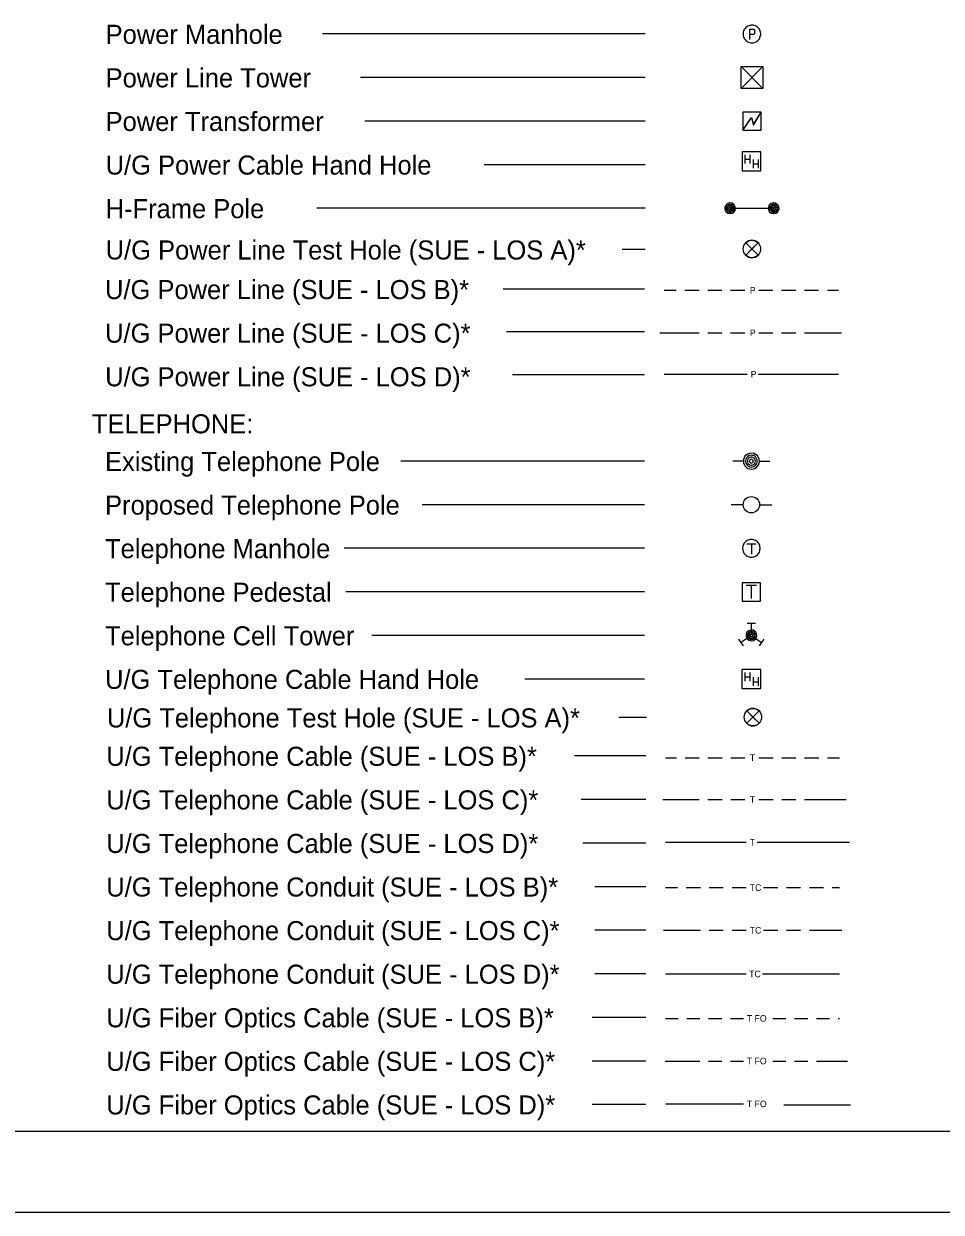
# Model space of a CAD drawing. Extents: x 1552903 to 1553044, y 811448 to 811540.
# Drawn here: x 1552973.4 to 1553008.81, y 811448.42 to 811494.28 of the extents above; entities that cross this region are included whole.
import ezdxf

# ---------------------------------------------------------------- set-up
doc = ezdxf.new("R2010")
doc.units = 0
for name, color, linetype in [('Exist DTM Breakline', 7, 'Continuous'), ('Exist Structure Major Bridge WW', 7, 'Continuous'), ('Exist Utilities Power Test Hole SUE LOS A CELL', 7, 'Continuous'), ('Exist Utilities Telephone Test Hole SUE LOS A CELL', 7, 'Continuous'), ('z - Construction', 7, 'Continuous')]:
    doc.layers.add(name, color=color, linetype=linetype)

msp = doc.modelspace()

# ---------------------------------------------------------------- linework, layer by layer
at = {"layer": 'Exist DTM Breakline'}
for p, q in [((1553001.602, 811494.039), (1553001.602, 811493.895)), ((1552997.385, 811493.884), (1552984.928, 811493.884)), ((1553001.574, 811493.867), (1553001.421, 811493.867)), ((1553001.928, 811492.624), (1553001.088, 811491.784)), ((1553001.928, 811491.784), (1553001.088, 811492.624)), ((1552997.385, 811492.202), (1552986.399, 811492.202)), ((1552997.385, 811490.521), (1552986.569, 811490.521)), ((1553001.231, 811489.225), (1553001.231, 811488.886)), ((1553001.231, 811489.053), (1553001.424, 811489.053)), ((1553001.424, 811489.225), (1553001.424, 811488.886)), ((1553001.554, 811489.041), (1553001.554, 811488.702)), ((1553001.554, 811488.868), (1553001.748, 811488.868)), ((1553001.748, 811489.041), (1553001.748, 811488.702)), ((1552997.385, 811488.839), (1552991.172, 811488.839)), ((1552997.385, 811487.158), (1552984.715, 811487.158)), ((1553000.665, 811487.158), (1553002.347, 811487.158)), ((1552997.385, 811485.562), (1552996.491, 811485.562)), ((1552997.362, 811484.035), (1552991.904, 811484.035)), ((1552998.12, 811483.993), (1552998.582, 811483.993)), ((1552998.919, 811483.993), (1552999.465, 811483.993)), ((1552999.801, 811483.993), (1553000.348, 811483.993)), ((1553000.684, 811483.993), (1553001.231, 811483.993)), ((1553001.769, 811483.993), (1553002.315, 811483.993)), ((1553002.652, 811483.993), (1553003.198, 811483.993)), ((1553003.534, 811483.993), (1553004.081, 811483.993)), ((1553004.417, 811483.993), (1553004.846, 811483.993)), ((1552997.362, 811482.385), (1552992.033, 811482.385)), ((1552997.95, 811482.353), (1552999.465, 811482.353)), ((1552999.801, 811482.353), (1553000.348, 811482.353)), ((1553000.684, 811482.353), (1553001.231, 811482.353)), ((1553001.769, 811482.353), (1553002.315, 811482.353)), ((1553002.652, 811482.353), (1553003.198, 811482.353)), ((1553003.534, 811482.353), (1553004.966, 811482.353)), ((1552997.362, 811480.736), (1552992.259, 811480.736)), ((1552998.12, 811480.759), (1553001.322, 811480.759)), ((1553001.743, 811480.759), (1553004.846, 811480.759)), ((1552997.362, 811477.402), (1552987.955, 811477.402)), ((1553001.173, 811477.402), (1553000.769, 811477.402)), ((1553001.793, 811477.402), (1553002.197, 811477.402)), ((1552997.362, 811475.72), (1552988.781, 811475.72)), ((1553001.171, 811475.719), (1553000.698, 811475.719)), ((1553001.801, 811475.719), (1553002.274, 811475.719)), ((1553001.658, 811474.197), (1553001.311, 811474.197)), ((1553001.483, 811474.197), (1553001.483, 811473.815)), ((1552997.362, 811474.039), (1552985.771, 811474.039)), ((1552997.362, 811472.357), (1552985.83, 811472.357)), ((1553001.286, 811472.611), (1553001.68, 811472.611)), ((1553001.483, 811472.104), (1553001.483, 811472.611)), ((1553001.325, 811471.152), (1553001.641, 811471.152)), ((1553001.483, 811470.883), (1553001.483, 811471.152)), ((1552997.362, 811470.676), (1552986.833, 811470.676)), ((1553001.184, 811470.274), (1553001.003, 811470.532)), ((1553001.314, 811470.557), (1553001.094, 811470.403)), ((1553001.653, 811470.558), (1553001.873, 811470.403)), ((1553001.963, 811470.533), (1553001.782, 811470.274)), ((1553001.225, 811469.249), (1553001.225, 811468.91)), ((1553001.419, 811469.249), (1553001.419, 811468.91)), ((1552997.362, 811468.994), (1552992.735, 811468.994)), ((1553001.225, 811469.076), (1553001.419, 811469.076)), ((1553001.549, 811469.064), (1553001.549, 811468.725)), ((1553001.549, 811468.891), (1553001.742, 811468.891)), ((1553001.742, 811469.064), (1553001.742, 811468.725)), ((1552997.431, 811467.508), (1552996.367, 811467.508)), ((1552997.408, 811466.026), (1552994.652, 811466.026)), ((1552998.166, 811465.959), (1552998.588, 811465.959)), ((1552998.925, 811465.959), (1552999.471, 811465.959)), ((1552999.807, 811465.959), (1553000.354, 811465.959)), ((1553000.69, 811465.959), (1553001.237, 811465.959)), ((1553001.775, 811465.959), (1553002.321, 811465.959)), ((1553002.658, 811465.959), (1553003.204, 811465.959)), ((1553003.54, 811465.959), (1553004.087, 811465.959)), ((1553004.423, 811465.959), (1553004.892, 811465.959)), ((1552997.408, 811464.345), (1552994.917, 811464.345)), ((1552998.061, 811464.345), (1552999.471, 811464.345)), ((1552999.807, 811464.345), (1553000.354, 811464.345)), ((1553000.69, 811464.345), (1553001.237, 811464.345)), ((1553001.775, 811464.345), (1553002.321, 811464.345)), ((1553002.658, 811464.345), (1553003.204, 811464.345)), ((1553003.54, 811464.345), (1553005.141, 811464.345)), ((1552997.408, 811462.663), (1552994.982, 811462.663)), ((1552998.166, 811462.693), (1553001.287, 811462.693)), ((1553001.708, 811462.693), (1553005.271, 811462.693)), ((1552997.408, 811460.982), (1552995.435, 811460.982)), ((1552998.166, 811460.946), (1552998.636, 811460.946)), ((1552998.972, 811460.946), (1552999.518, 811460.946)), ((1552999.855, 811460.946), (1553000.401, 811460.946)), ((1553000.737, 811460.946), (1553001.284, 811460.946)), ((1553001.957, 811460.946), (1553002.503, 811460.946)), ((1553002.839, 811460.946), (1553003.386, 811460.946)), ((1553003.722, 811460.946), (1553004.269, 811460.946)), ((1553004.605, 811460.946), (1553004.892, 811460.946)), ((1552997.408, 811459.3), (1552995.435, 811459.3)), ((1552998.086, 811459.3), (1552999.518, 811459.3)), ((1552999.855, 811459.3), (1553000.401, 811459.3)), ((1553000.737, 811459.3), (1553001.284, 811459.3)), ((1553001.957, 811459.3), (1553002.503, 811459.3)), ((1553002.839, 811459.3), (1553003.386, 811459.3)), ((1553003.722, 811459.3), (1553004.973, 811459.3)), ((1552997.408, 811457.619), (1552995.435, 811457.619)), ((1552998.166, 811457.614), (1553001.284, 811457.614)), ((1553001.915, 811457.614), (1553004.892, 811457.614)), ((1552997.408, 811455.937), (1552995.338, 811455.937)), ((1552998.166, 811455.9), (1552998.657, 811455.9)), ((1552998.993, 811455.9), (1552999.497, 811455.9)), ((1552999.834, 811455.9), (1553000.338, 811455.9)), ((1553000.674, 811455.9), (1553001.179, 811455.9)), ((1553002.314, 811455.9), (1553002.818, 811455.9)), ((1553003.155, 811455.9), (1553003.659, 811455.9)), ((1553003.996, 811455.9), (1553004.5, 811455.9)), ((1553004.836, 811455.9), (1553004.892, 811455.9)), ((1552997.408, 811454.255), (1552995.338, 811454.255)), ((1552998.15, 811454.255), (1552999.497, 811454.255)), ((1552999.834, 811454.255), (1553000.338, 811454.255)), ((1553000.674, 811454.255), (1553001.179, 811454.255)), ((1553002.314, 811454.255), (1553002.818, 811454.255)), ((1553003.155, 811454.255), (1553003.659, 811454.255)), ((1553003.996, 811454.255), (1553005.199, 811454.255)), ((1552997.408, 811452.574), (1552995.338, 811452.574)), ((1552998.166, 811452.601), (1553001.182, 811452.601)), ((1553002.737, 811452.569), (1553005.312, 811452.569))]:
    msp.add_line(p, q, dxfattribs=at)
for points in [[(1553001.506, 811494.225), (1553001.462, 811494.222), (1553001.421, 811494.214), (1553001.38, 811494.201), (1553001.342, 811494.181), (1553001.307, 811494.16), (1553001.274, 811494.132), (1553001.244, 811494.1), (1553001.219, 811494.067), (1553001.197, 811494.029), (1553001.184, 811493.988), (1553001.173, 811493.947), (1553001.167, 811493.906), (1553001.167, 811493.862), (1553001.173, 811493.821), (1553001.184, 811493.777), (1553001.197, 811493.739), (1553001.219, 811493.701), (1553001.244, 811493.668), (1553001.274, 811493.635), (1553001.307, 811493.608), (1553001.342, 811493.586), (1553001.38, 811493.567), (1553001.421, 811493.553), (1553001.465, 811493.545), (1553001.506, 811493.542), (1553001.55, 811493.545), (1553001.591, 811493.553), (1553001.632, 811493.567), (1553001.67, 811493.586), (1553001.705, 811493.608), (1553001.738, 811493.635), (1553001.768, 811493.668), (1553001.793, 811493.701), (1553001.815, 811493.739), (1553001.828, 811493.78), (1553001.839, 811493.821), (1553001.845, 811493.862), (1553001.845, 811493.906), (1553001.839, 811493.947), (1553001.828, 811493.99), (1553001.815, 811494.029), (1553001.793, 811494.067), (1553001.768, 811494.1), (1553001.738, 811494.132), (1553001.705, 811494.16), (1553001.67, 811494.181), (1553001.632, 811494.201), (1553001.591, 811494.214), (1553001.547, 811494.222), (1553001.506, 811494.225)], [(1553001.421, 811493.665), (1553001.421, 811493.867), (1553001.421, 811494.067), (1553001.574, 811494.067)], [(1553001.574, 811494.067), (1553001.585, 811494.064), (1553001.593, 811494.059), (1553001.599, 811494.05), (1553001.602, 811494.039)], [(1553001.602, 811493.895), (1553001.599, 811493.884), (1553001.593, 811493.876), (1553001.585, 811493.87), (1553001.574, 811493.867)], [(1553001.928, 811491.784), (1553001.088, 811491.784), (1553001.088, 811492.624), (1553001.928, 811492.624), (1553001.928, 811491.784), (1553001.088, 811491.784), (1553001.088, 811492.624), (1553001.928, 811492.624), (1553001.928, 811491.784)], [(1553001.156, 811490.17), (1553001.486, 811490.646), (1553001.567, 811490.387), (1553001.856, 811490.871)], [(1553001.156, 811490.17), (1553001.489, 811490.665), (1553001.564, 811490.368), (1553001.856, 811490.871)], [(1553001.156, 811490.17), (1553001.856, 811490.17), (1553001.856, 811490.871), (1553001.156, 811490.871), (1553001.156, 811490.17)], [(1553001.127, 811488.609), (1553001.85, 811488.609), (1553001.85, 811489.333), (1553001.127, 811489.333), (1553001.127, 811488.609)], [(1553000.818, 811487.158), (1553000.814, 811487.195), (1553000.802, 811487.228), (1553000.781, 811487.257), (1553000.756, 811487.282), (1553000.727, 811487.298), (1553000.69, 811487.307), (1553000.657, 811487.311), (1553000.62, 811487.302), (1553000.586, 811487.29), (1553000.562, 811487.269), (1553000.537, 811487.24), (1553000.52, 811487.211), (1553000.512, 811487.174), (1553000.512, 811487.141), (1553000.52, 811487.104), (1553000.537, 811487.075), (1553000.562, 811487.046), (1553000.586, 811487.025), (1553000.62, 811487.013), (1553000.657, 811487.004), (1553000.69, 811487.009), (1553000.727, 811487.017), (1553000.756, 811487.033), (1553000.781, 811487.058), (1553000.802, 811487.087), (1553000.814, 811487.12), (1553000.818, 811487.158)], [(1553000.769, 811487.158), (1553000.764, 811487.187), (1553000.752, 811487.215), (1553000.731, 811487.236), (1553000.707, 811487.253), (1553000.682, 811487.261), (1553000.649, 811487.261), (1553000.624, 811487.253), (1553000.599, 811487.236), (1553000.578, 811487.215), (1553000.566, 811487.187), (1553000.562, 811487.158), (1553000.566, 811487.129), (1553000.578, 811487.1), (1553000.599, 811487.079), (1553000.624, 811487.062), (1553000.649, 811487.054), (1553000.682, 811487.054), (1553000.707, 811487.062), (1553000.731, 811487.079), (1553000.752, 811487.1), (1553000.764, 811487.129), (1553000.769, 811487.158)], [(1553000.715, 811487.158), (1553000.711, 811487.178), (1553000.698, 811487.195), (1553000.682, 811487.203), (1553000.661, 811487.207), (1553000.64, 811487.199), (1553000.624, 811487.187), (1553000.615, 811487.166), (1553000.615, 811487.149), (1553000.624, 811487.129), (1553000.64, 811487.116), (1553000.661, 811487.108), (1553000.682, 811487.112), (1553000.698, 811487.12), (1553000.711, 811487.137), (1553000.715, 811487.158)], [(1553002.5, 811487.158), (1553002.496, 811487.195), (1553002.483, 811487.228), (1553002.463, 811487.257), (1553002.438, 811487.282), (1553002.409, 811487.298), (1553002.371, 811487.307), (1553002.338, 811487.311), (1553002.301, 811487.302), (1553002.268, 811487.29), (1553002.243, 811487.269), (1553002.219, 811487.24), (1553002.202, 811487.211), (1553002.194, 811487.174), (1553002.194, 811487.141), (1553002.202, 811487.104), (1553002.219, 811487.075), (1553002.243, 811487.046), (1553002.268, 811487.025), (1553002.301, 811487.013), (1553002.338, 811487.004), (1553002.371, 811487.009), (1553002.409, 811487.017), (1553002.438, 811487.033), (1553002.463, 811487.058), (1553002.483, 811487.087), (1553002.496, 811487.12), (1553002.5, 811487.158)], [(1553002.45, 811487.158), (1553002.446, 811487.187), (1553002.434, 811487.215), (1553002.413, 811487.236), (1553002.388, 811487.253), (1553002.363, 811487.261), (1553002.33, 811487.261), (1553002.305, 811487.253), (1553002.28, 811487.236), (1553002.26, 811487.215), (1553002.247, 811487.187), (1553002.243, 811487.158), (1553002.247, 811487.129), (1553002.26, 811487.1), (1553002.28, 811487.079), (1553002.305, 811487.062), (1553002.33, 811487.054), (1553002.363, 811487.054), (1553002.388, 811487.062), (1553002.413, 811487.079), (1553002.434, 811487.1), (1553002.446, 811487.129), (1553002.45, 811487.158)], [(1553002.396, 811487.158), (1553002.392, 811487.178), (1553002.38, 811487.195), (1553002.363, 811487.203), (1553002.343, 811487.207), (1553002.322, 811487.199), (1553002.305, 811487.187), (1553002.297, 811487.166), (1553002.297, 811487.149), (1553002.305, 811487.129), (1553002.322, 811487.116), (1553002.343, 811487.108), (1553002.363, 811487.112), (1553002.38, 811487.12), (1553002.392, 811487.137), (1553002.396, 811487.158)], [(1553001.713, 811477.402), (1553001.706, 811477.458), (1553001.688, 811477.507), (1553001.657, 811477.551), (1553001.619, 811477.588), (1553001.576, 811477.613), (1553001.52, 811477.625), (1553001.47, 811477.632), (1553001.415, 811477.619), (1553001.365, 811477.601), (1553001.328, 811477.57), (1553001.291, 811477.526), (1553001.266, 811477.483), (1553001.253, 811477.427), (1553001.253, 811477.377), (1553001.266, 811477.321), (1553001.291, 811477.278), (1553001.328, 811477.234), (1553001.365, 811477.203), (1553001.415, 811477.185), (1553001.47, 811477.172), (1553001.52, 811477.179), (1553001.576, 811477.191), (1553001.619, 811477.216), (1553001.657, 811477.253), (1553001.688, 811477.297), (1553001.706, 811477.346), (1553001.713, 811477.402)], [(1553001.638, 811477.402), (1553001.632, 811477.445), (1553001.613, 811477.489), (1553001.582, 811477.52), (1553001.545, 811477.545), (1553001.508, 811477.557), (1553001.458, 811477.557), (1553001.421, 811477.545), (1553001.384, 811477.52), (1553001.353, 811477.489), (1553001.334, 811477.445), (1553001.328, 811477.402), (1553001.334, 811477.359), (1553001.353, 811477.315), (1553001.384, 811477.284), (1553001.421, 811477.259), (1553001.458, 811477.247), (1553001.508, 811477.247), (1553001.545, 811477.259), (1553001.582, 811477.284), (1553001.613, 811477.315), (1553001.632, 811477.359), (1553001.638, 811477.402)], [(1553001.557, 811477.402), (1553001.551, 811477.433), (1553001.533, 811477.458), (1553001.508, 811477.47), (1553001.477, 811477.476), (1553001.446, 811477.464), (1553001.421, 811477.445), (1553001.408, 811477.415), (1553001.408, 811477.389), (1553001.421, 811477.359), (1553001.446, 811477.34), (1553001.477, 811477.328), (1553001.508, 811477.334), (1553001.533, 811477.346), (1553001.551, 811477.371), (1553001.557, 811477.402)], [(1553001.483, 811474.38), (1553001.439, 811474.377), (1553001.398, 811474.369), (1553001.357, 811474.356), (1553001.319, 811474.336), (1553001.284, 811474.315), (1553001.251, 811474.287), (1553001.221, 811474.255), (1553001.196, 811474.222), (1553001.174, 811474.184), (1553001.161, 811474.143), (1553001.15, 811474.102), (1553001.144, 811474.061), (1553001.144, 811474.017), (1553001.15, 811473.976), (1553001.161, 811473.932), (1553001.174, 811473.894), (1553001.196, 811473.856), (1553001.221, 811473.823), (1553001.251, 811473.79), (1553001.284, 811473.763), (1553001.319, 811473.741), (1553001.357, 811473.722), (1553001.398, 811473.708), (1553001.442, 811473.7), (1553001.483, 811473.698), (1553001.527, 811473.7), (1553001.568, 811473.708), (1553001.609, 811473.722), (1553001.647, 811473.741), (1553001.682, 811473.763), (1553001.715, 811473.79), (1553001.745, 811473.823), (1553001.77, 811473.856), (1553001.792, 811473.894), (1553001.805, 811473.935), (1553001.816, 811473.976), (1553001.822, 811474.017), (1553001.822, 811474.061), (1553001.816, 811474.102), (1553001.805, 811474.145), (1553001.792, 811474.184), (1553001.77, 811474.222), (1553001.745, 811474.255), (1553001.715, 811474.287), (1553001.682, 811474.315), (1553001.647, 811474.336), (1553001.609, 811474.356), (1553001.568, 811474.369), (1553001.524, 811474.377), (1553001.483, 811474.38)], [(1553001.129, 811472.003), (1553001.837, 811472.003), (1553001.837, 811472.711), (1553001.129, 811472.711), (1553001.129, 811472.003)], [(1553001.636, 811470.676), (1553001.632, 811470.713), (1553001.619, 811470.746), (1553001.599, 811470.775), (1553001.574, 811470.8), (1553001.545, 811470.816), (1553001.508, 811470.825), (1553001.475, 811470.829), (1553001.437, 811470.821), (1553001.404, 811470.808), (1553001.38, 811470.787), (1553001.355, 811470.758), (1553001.338, 811470.73), (1553001.33, 811470.692), (1553001.33, 811470.659), (1553001.338, 811470.622), (1553001.355, 811470.593), (1553001.38, 811470.564), (1553001.404, 811470.543), (1553001.437, 811470.531), (1553001.475, 811470.523), (1553001.508, 811470.527), (1553001.545, 811470.535), (1553001.574, 811470.552), (1553001.599, 811470.576), (1553001.619, 811470.605), (1553001.632, 811470.639), (1553001.636, 811470.676)], [(1553001.586, 811470.676), (1553001.582, 811470.705), (1553001.57, 811470.734), (1553001.549, 811470.754), (1553001.524, 811470.771), (1553001.5, 811470.779), (1553001.466, 811470.779), (1553001.442, 811470.771), (1553001.417, 811470.754), (1553001.396, 811470.734), (1553001.384, 811470.705), (1553001.38, 811470.676), (1553001.384, 811470.647), (1553001.396, 811470.618), (1553001.417, 811470.597), (1553001.442, 811470.581), (1553001.466, 811470.572), (1553001.5, 811470.572), (1553001.524, 811470.581), (1553001.549, 811470.597), (1553001.57, 811470.618), (1553001.582, 811470.647), (1553001.586, 811470.676)], [(1553001.533, 811470.676), (1553001.528, 811470.696), (1553001.516, 811470.713), (1553001.5, 811470.721), (1553001.479, 811470.725), (1553001.458, 811470.717), (1553001.442, 811470.705), (1553001.433, 811470.684), (1553001.433, 811470.667), (1553001.442, 811470.647), (1553001.458, 811470.634), (1553001.479, 811470.626), (1553001.5, 811470.63), (1553001.516, 811470.639), (1553001.528, 811470.655), (1553001.533, 811470.676)], [(1553001.121, 811468.632), (1553001.845, 811468.632), (1553001.845, 811469.356), (1553001.121, 811469.356), (1553001.121, 811468.632)]]:
    msp.add_lwpolyline(points, dxfattribs=at)
for points in [[(1553000.665, 811486.951), (1553000.752, 811486.967), (1553000.81, 811487.009), (1553000.856, 811487.067), (1553000.872, 811487.145), (1553000.864, 811487.22), (1553000.822, 811487.294), (1553000.74, 811487.356), (1553000.644, 811487.364), (1553000.562, 811487.34), (1553000.496, 811487.282), (1553000.462, 811487.203), (1553000.462, 811487.112), (1553000.496, 811487.033), (1553000.57, 811486.971)], [(1553002.347, 811486.951), (1553002.434, 811486.967), (1553002.492, 811487.009), (1553002.537, 811487.067), (1553002.554, 811487.145), (1553002.545, 811487.22), (1553002.504, 811487.294), (1553002.421, 811487.356), (1553002.326, 811487.364), (1553002.243, 811487.34), (1553002.177, 811487.282), (1553002.144, 811487.203), (1553002.144, 811487.112), (1553002.177, 811487.033), (1553002.252, 811486.971)], [(1553001.483, 811477.092), (1553001.613, 811477.116), (1553001.7, 811477.179), (1553001.769, 811477.266), (1553001.793, 811477.383), (1553001.781, 811477.495), (1553001.719, 811477.607), (1553001.595, 811477.7), (1553001.452, 811477.712), (1553001.328, 811477.675), (1553001.229, 811477.588), (1553001.179, 811477.47), (1553001.179, 811477.334), (1553001.229, 811477.216), (1553001.34, 811477.123)], [(1553001.483, 811470.469), (1553001.57, 811470.485), (1553001.628, 811470.527), (1553001.673, 811470.585), (1553001.69, 811470.663), (1553001.682, 811470.738), (1553001.64, 811470.812), (1553001.557, 811470.874), (1553001.462, 811470.883), (1553001.38, 811470.858), (1553001.313, 811470.8), (1553001.28, 811470.721), (1553001.28, 811470.63), (1553001.313, 811470.552), (1553001.388, 811470.489)]]:
    msp.add_lwpolyline(points, close=True, dxfattribs=at)
msp.add_circle((1553001.483, 811475.72), 0.315, dxfattribs=at)
at = {"layer": 'Exist Structure Major Bridge WW'}
msp.add_line((1552905.688, 811451.545), (1553041.103, 811451.545), dxfattribs=at)
at = {"layer": 'Exist Utilities Power Test Hole SUE LOS A CELL'}
for points in [[(1553001.742, 811485.826), (1553001.266, 811485.351), (1553001.504, 811485.588), (1553001.266, 811485.826), (1553001.742, 811485.351)], [(1553001.266, 811485.826), (1553001.504, 811485.588), (1553001.742, 811485.826)], [(1553001.742, 811485.351), (1553001.504, 811485.588), (1553001.266, 811485.351)]]:
    msp.add_lwpolyline(points, dxfattribs=at)
msp.add_circle((1553001.504, 811485.588), 0.336, dxfattribs=at)
for start, end in [(45, 135), (225, 315)]:
    msp.add_arc((1553001.504, 811485.588), 0.336, start, end, dxfattribs=at)
at = {"layer": 'Exist Utilities Telephone Test Hole SUE LOS A CELL'}
for points in [[(1553001.781, 811467.761), (1553001.306, 811467.286), (1553001.544, 811467.524), (1553001.306, 811467.761), (1553001.781, 811467.286)], [(1553001.306, 811467.761), (1553001.544, 811467.524), (1553001.781, 811467.761)], [(1553001.781, 811467.286), (1553001.544, 811467.524), (1553001.306, 811467.286)]]:
    msp.add_lwpolyline(points, dxfattribs=at)
msp.add_circle((1553001.544, 811467.524), 0.336, dxfattribs=at)
for start, end in [(45, 135), (225, 315)]:
    msp.add_arc((1553001.544, 811467.524), 0.336, start, end, dxfattribs=at)
at = {"layer": 'z - Construction'}
msp.add_line((1552902.563, 811448.42), (1553044.23, 811448.42), dxfattribs=at)

# ---------------------------------------------------------------- texts
at = {"layer": 'Exist DTM Breakline'}
for s, height, p in [('Power Manhole', 0.73569, (1552976.557, 811493.502)), ('Power Line Tower', 0.73569, (1552976.557, 811491.822)), ('Power Transformer', 0.73569, (1552976.556, 811490.14)), ('U/G Power Cable Hand Hole', 0.73569, (1552976.558, 811488.458)), ('H-Frame Pole', 0.73569, (1552976.558, 811486.776)), ('U/G Power Line Test Hole (SUE - LOS A)*', 0.73569, (1552976.558, 811485.181)), ('U/G Power Line (SUE - LOS B)*', 0.73569, (1552976.535, 811483.653)), ('P', 0.252, (1553001.424, 811483.867)), ('U/G Power Line (SUE - LOS C)*', 0.73569, (1552976.537, 811481.971)), ('P', 0.252, (1553001.424, 811482.227)), ('U/G Power Line (SUE - LOS D)*', 0.73569, (1552976.539, 811480.288)), ('P', 0.252, (1553001.457, 811480.633)), ('TELEPHONE:', 0.7357, (1552976.025, 811478.474)), ('Existing Telephone Pole', 0.73569, (1552976.535, 811477.02)), ('Proposed Telephone Pole', 0.73569, (1552976.535, 811475.339)), ('Telephone Manhole', 0.73569, (1552976.535, 811473.657)), ('Telephone Pedestal', 0.73569, (1552976.535, 811471.976)), ('Telephone Cell Tower', 0.73569, (1552976.536, 811470.294)), ('U/G Telephone Cable Hand Hole', 0.73569, (1552976.536, 811468.613)), ('U/G Telephone Test Hole (SUE - LOS A)*', 0.73569, (1552976.605, 811467.126)), ('U/G Telephone Cable (SUE - LOS B)*', 0.73569, (1552976.582, 811465.645)), ('T', 0.252, (1553001.426, 811465.833)), ('U/G Telephone Cable (SUE - LOS C)*', 0.73569, (1552976.582, 811463.963)), ('T', 0.252, (1553001.426, 811464.219)), ('U/G Telephone Cable (SUE - LOS D)*', 0.73569, (1552976.582, 811462.282)), ('T', 0.252, (1553001.417, 811462.567)), ('U/G Telephone Conduit (SUE - LOS B)*', 0.73569, (1552976.582, 811460.6)), ('TC', 0.2522, (1553001.419, 811460.82)), ('U/G Telephone Conduit (SUE - LOS C)*', 0.73569, (1552976.582, 811458.919)), ('TC', 0.2522, (1553001.419, 811459.174)), ('U/G Telephone Conduit (SUE - LOS D)*', 0.73569, (1552976.582, 811457.237)), ('TC', 0.2522, (1553001.398, 811457.488)), ('U/G Fiber Optics Cable (SUE - LOS B)*', 0.73569, (1552976.582, 811455.555)), ('T FO', 0.2522, (1553001.305, 811455.774)), ('U/G Fiber Optics Cable (SUE - LOS C)*', 0.73569, (1552976.582, 811453.874)), ('T FO', 0.2522, (1553001.305, 811454.129)), ('U/G Fiber Optics Cable (SUE - LOS D)*', 0.73569, (1552976.582, 811452.192)), ('T FO', 0.2522, (1553001.308, 811452.475))]:
    msp.add_text(s, height=height, dxfattribs=at).set_placement(p)

doc.saveas('drawing.dxf')
